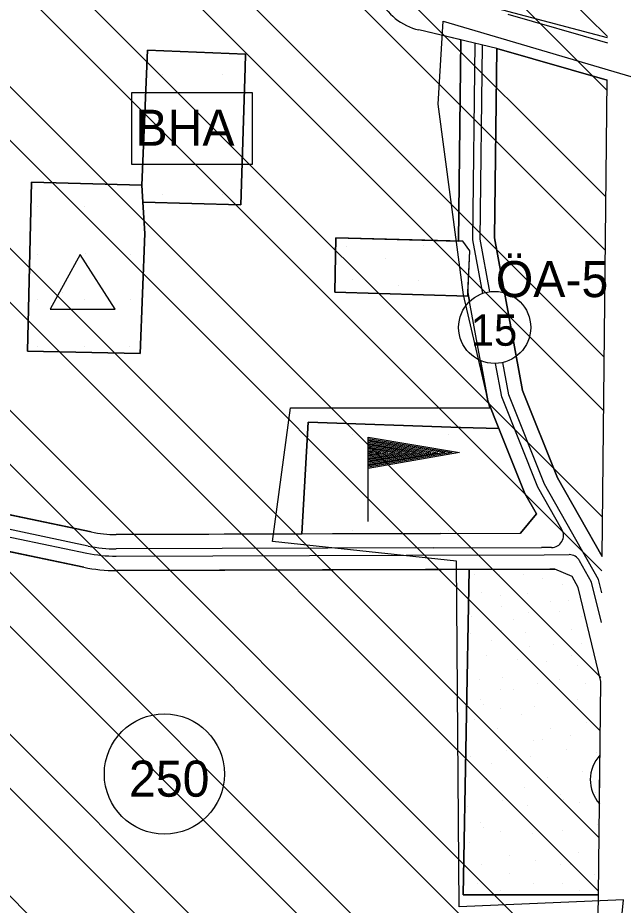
# Model space of a CAD drawing. Extents: x 409341 to 428634, y 4447481 to 4463281.
# Drawn here: x 421057.8 to 421309.7, y 4458160.3 to 4458529.4 of the extents above; entities that cross this region are included whole.
import ezdxf

# ---------------------------------------------------------------- set-up
doc = ezdxf.new("R2010")
doc.units = 0
for name, color, linetype in [('ADA', 7, 'Continuous'), ('ADAKENARI', 7, 'Continuous'), ('Default', 7, 'Continuous'), ('KALDIRIM', 7, 'Continuous'), ('KD_DAIRE', 7, 'Continuous'), ('KD_YGEN', 7, 'Continuous'), ('LJ_SEMBOL', 7, 'Continuous'), ('OA5', 7, 'Continuous'), ('OSB', 7, 'Continuous'), ('PL_AYA_PARK_DINLENME', 7, 'Continuous'), ('PL_EĞİTİM', 7, 'Continuous'), ('PL_K_BHA', 7, 'Continuous'), ('PL_KON_MEV_250', 7, 'Continuous'), ('PL_KON_ONE_250', 7, 'Continuous'), ('PL_KON_ONE_350', 7, 'Continuous'), ('PL_SAY_SPOR', 7, 'Continuous'), ('SM_DAIRE', 7, 'Continuous'), ('SM_TAKS', 7, 'Continuous'), ('SN_TR_SIVILASMA', 7, 'Continuous'), ('TR_EĞİTİM', 7, 'Continuous'), ('TR_KENTSELSPOR', 7, 'Continuous'), ('TR_ORTAGELISME', 7, 'Continuous'), ('TR_ORTAYOGUNKONUT', 7, 'Continuous'), ('TR_PARKALANI', 7, 'Continuous'), ('TR_YONETIMMERK', 7, 'Continuous')]:
    doc.layers.add(name, color=color, linetype=linetype)

# ---------------------------------------------------------------- blocks, each defined once
blk = doc.blocks.new('POINT_DISPLAY')
at = {"layer": 'Default'}
blk.add_line((0, 0), (0, 0), dxfattribs=at)

msp = doc.modelspace()

# ---------------------------------------------------------------- linework, layer by layer
at = {"layer": 'ADA'}
for p, q in [((421245.58, 4458299.98), (421243.14, 4458164.61)), ((421243.14, 4458164.61), (421299.42, 4458164.61))]:
    msp.add_line(p, q, dxfattribs=at)
for points in [[(421109.81, 4458452.73), (421150.57, 4458451.6), (421152.47, 4458508.66), (421152.6, 4458514.27), (421111.77, 4458515.9), (421109.38, 4458459.74)], [(421109.38, 4458459.74), (421063.47, 4458461.09), (421061.84, 4458390.69), (421108.68, 4458389.76), (421110.63, 4458439.7), (421109.81, 4458452.73)]]:
    msp.add_lwpolyline(points, close=True, dxfattribs=at)
msp.add_lwpolyline([(421176.05, 4458314.75), (421178.62, 4458361.17), (421241.98, 4458359.06), (421258.01, 4458358.52)], dxfattribs=at)
at = {"layer": 'ADAKENARI'}
for p, q in [((421261.66, 4458530.99), (421303.12, 4458518.98)), ((421257.09, 4458516.7), (421224.68, 4458524.38)), ((421257.09, 4458516.7), (421302.96, 4458503.42)), ((421088.37, 4458315.57), (421031.06, 4458327.58)), ((420984.64, 4458321.99), (421085.29, 4458300.89)), ((421233.73, 4458314.94), (421098.79, 4458314.5)), ((421233.73, 4458314.94), (421266.9, 4458315.05)), ((421098.84, 4458299.5), (421279.13, 4458300.09)), ((421098.84, 4458299.5), (421227.39, 4458299.92)), ((421279.13, 4458300.09), (421281.2, 4458300.1))]:
    msp.add_line(p, q, dxfattribs=at)
for points in [[(421242.13, 4458520.23), (421241.19, 4458436.6), (421241.2, 4458436.53)], [(421267.85, 4458374.33), (421256.2, 4458437.88), (421257.09, 4458516.7)], [(421245.11, 4458415.17), (421245.8, 4458411.43)], [(421250.3, 4458386.85), (421253.37, 4458370.15), (421258.01, 4458358.52), (421268.78, 4458331.58), (421273.57, 4458323.13), (421266.9, 4458315.05)], [(421300.89, 4458305.33), (421282.33, 4458338.09), (421267.85, 4458374.33)], [(421300.35, 4458253.34), (421290.92, 4458292.51), (421288.4, 4458296.96), (421281.2, 4458300.1)]]:
    msp.add_lwpolyline(points, dxfattribs=at)
msp.add_lwpolyline([(421190.16, 4458437.9), (421189.73, 4458415.29), (421245.05, 4458413.63), (421245.85, 4458432.5), (421242.99, 4458436.48)], close=True, dxfattribs=at)
for centre, radius, start, end in [((421230.47, 4458548.7), 25, 206.131, 256.6075), ((421098.63, 4458364.5), 50, 258.1579, 270.186), ((421098.63, 4458364.5), 65, 258.1579, 270.186)]:
    msp.add_arc(centre, radius, start, end, dxfattribs=at)
at = {"layer": 'Default'}
msp.add_lwpolyline([(421297.69, 4458041.38), (421309.86, 4458162.54), (421241.45, 4458159.64), (421240.3, 4458303.41), (421163.77, 4458311.52), (421171.31, 4458367.18), (421254.21, 4458367.18), (421243.19, 4458414.13), (421232.76, 4458493.55), (421234.79, 4458528.04), (421444.06, 4458466.31), (421567.25, 4458468.77)], dxfattribs=at)
at = {"layer": 'KALDIRIM'}
for p, q in [((420967.32, 4458331.75), (421086.52, 4458306.76)), ((421087.13, 4458309.69), (421029.83, 4458321.71)), ((421230.92, 4458308.93), (421098.81, 4458308.5)), ((421230.92, 4458308.93), (421275.65, 4458309.08)), ((421279.85, 4458309.09), (421275.65, 4458309.08)), ((421098.82, 4458305.5), (421219.35, 4458305.89)), ((421219.35, 4458305.89), (421276.81, 4458306.08)), ((421276.81, 4458306.08), (421287.17, 4458306.11)), ((421300.61, 4458277.91), (421296.56, 4458294.73)), ((421300.73, 4458290.19), (421299.37, 4458295.84))]:
    msp.add_line(p, q, dxfattribs=at)
for points in [[(421251.28, 4458414.8), (421247.19, 4458437.11), (421248.11, 4458518.83)], [(421254.2, 4458415.5), (421250.2, 4458437.37), (421251.11, 4458517.98)], [(421259.16, 4458371.82), (421256.63, 4458385.64)], [(421262.06, 4458372.66), (421259.61, 4458386.03)], [(421284.19, 4458316.56), (421274.2, 4458334.19), (421259.16, 4458371.82)], [(421299.37, 4458295.84), (421276.91, 4458335.49), (421262.06, 4458372.66)], [(421296.56, 4458294.73), (421291.54, 4458303.58)]]:
    msp.add_lwpolyline(points, dxfattribs=at)
for centre, radius, start, end in [((421279.84, 4458314.09), 5, 270.186, 29.5377), ((421098.63, 4458364.5), 56, 258.1579, 270.186), ((421098.63, 4458364.5), 59, 258.1579, 270.186), ((421287.19, 4458301.11), 5, 29.5377, 90.186)]:
    msp.add_arc(centre, radius, start, end, dxfattribs=at)
at = {"layer": 'KD_DAIRE'}
msp.add_line((421299.82, 4458202.47), (421300.03, 4458222.74), dxfattribs=at)
msp.add_circle((421256.22, 4458400.64), 15, dxfattribs=at)
msp.add_arc((421310.98, 4458212.49), 15, 136.8791, 221.9252, dxfattribs=at)
at = {"layer": 'LJ_SEMBOL'}
for p, q in [((421083.85, 4458430.99), (421071.3, 4458408.18)), ((421098.32, 4458408.18), (421083.85, 4458430.99)), ((421071.3, 4458408.18), (421098.32, 4458408.18)), ((421203.57, 4458319.93), (421203.57, 4458354.93))]:
    msp.add_line(p, q, dxfattribs=at)
for points in [[(421105.29, 4458498.34), (421155.29, 4458498.34), (421155.29, 4458468.34), (421105.29, 4458468.34), (421105.29, 4458498.34), (421155.29, 4458498.34)], [(421203.57, 4458354.93), (421241.52, 4458348.55), (421203.57, 4458341.98)], [(421203.57, 4458354.42), (421238.55, 4458348.54), (421203.57, 4458342.49)], [(421203.57, 4458353.92), (421235.58, 4458348.54), (421203.57, 4458342.99)], [(421203.57, 4458353.41), (421232.61, 4458348.53), (421203.57, 4458343.5)], [(421203.57, 4458352.9), (421229.63, 4458348.52), (421203.57, 4458344.01)], [(421203.57, 4458352.4), (421226.66, 4458348.52), (421203.57, 4458344.52)], [(421203.57, 4458351.89), (421223.69, 4458348.51), (421203.57, 4458345.02)], [(421203.57, 4458351.38), (421220.72, 4458348.5), (421203.57, 4458345.53)], [(421203.57, 4458350.88), (421217.74, 4458348.49), (421203.57, 4458346.04)], [(421203.57, 4458350.37), (421214.77, 4458348.49), (421203.57, 4458346.55)], [(421203.57, 4458349.86), (421211.8, 4458348.48), (421203.57, 4458347.05)], [(421203.57, 4458349.35), (421208.83, 4458348.47), (421203.57, 4458347.56)], [(421203.57, 4458348.85), (421205.86, 4458348.46), (421203.57, 4458348.07)]]:
    msp.add_lwpolyline(points, dxfattribs=at)
at = {"layer": 'OSB'}
msp.add_lwpolyline([(421303.14, 4458521.03), (421213.37, 4458544.99), (420881.63, 4458557.8), (420391.63, 4458402.74)], dxfattribs=at)
at = {"layer": 'PL_AYA_PARK_DINLENME'}
msp.add_line((421299.42, 4458164.61), (421300.35, 4458253.34), dxfattribs=at)
for points in [[(421241.2, 4458436.53), (421190.16, 4458437.9), (421189.73, 4458415.29), (421245.05, 4458413.63), (421245.11, 4458415.17), (421245.85, 4458432.5), (421242.99, 4458436.48), (421241.2, 4458436.53)], [(421300.35, 4458253.34), (421290.92, 4458292.51), (421288.4, 4458296.96), (421281.2, 4458300.1), (421279.13, 4458300.09), (421245.58, 4458299.98), (421243.14, 4458164.61), (421299.42, 4458164.61)]]:
    msp.add_lwpolyline(points, dxfattribs=at)
at = {"layer": 'PL_EĞİTİM'}
msp.add_lwpolyline([(421109.81, 4458452.73), (421109.38, 4458459.74), (421063.47, 4458461.09), (421061.84, 4458390.69), (421108.68, 4458389.76), (421110.63, 4458439.7), (421109.81, 4458452.73)], dxfattribs=at)
at = {"layer": 'PL_K_BHA'}
msp.add_lwpolyline([(421109.38, 4458459.74), (421109.81, 4458452.73), (421150.57, 4458451.6), (421152.47, 4458508.66), (421152.6, 4458514.27), (421111.77, 4458515.9), (421109.38, 4458459.74)], dxfattribs=at)
at = {"layer": 'PL_KON_MEV_250'}
msp.add_line((421299.33, 4458155.94), (421299.42, 4458164.61), dxfattribs=at)
for points in [[(421085.29, 4458300.89), (420988.83, 4458321.11), (420988.83, 4458315.56), (420979.14, 4458315.7), (420960.46, 4458090.34)], [(421245.58, 4458299.98), (421227.39, 4458299.92), (421098.84, 4458299.5)], [(421299.42, 4458164.61), (421243.14, 4458164.61), (421245.58, 4458299.98)]]:
    msp.add_lwpolyline(points, dxfattribs=at)
msp.add_arc((421098.63, 4458364.5), 65, 258.1579, 270.186, dxfattribs=at)
at = {"layer": 'PL_KON_ONE_250'}
for points in [[(421245.11, 4458415.17), (421245.05, 4458413.63), (421189.73, 4458415.29), (421190.16, 4458437.9), (421241.2, 4458436.53), (421241.19, 4458436.6), (421242.13, 4458520.23), (421224.68, 4458524.38)], [(421109.38, 4458459.74), (421111.77, 4458515.9), (421152.6, 4458514.27), (421152.47, 4458508.66), (421150.57, 4458451.6), (421109.81, 4458452.73), (421110.63, 4458439.7), (421108.68, 4458389.76), (421061.84, 4458390.69), (421063.47, 4458461.09), (421109.38, 4458459.74)], [(421098.79, 4458314.5), (421176.05, 4458314.75), (421178.62, 4458361.17), (421241.98, 4458359.06), (421258.01, 4458358.52), (421253.37, 4458370.15), (421245.11, 4458415.17)], [(420943.04, 4458393.72), (420970.15, 4458344.23), (420967.66, 4458340.88), (421031.06, 4458327.58), (421088.37, 4458315.57)]]:
    msp.add_lwpolyline(points, dxfattribs=at)
for centre, radius, start, end in [((421230.47, 4458548.7), 25, 206.131, 256.6075), ((421098.63, 4458364.5), 50, 258.1579, 270.186)]:
    msp.add_arc(centre, radius, start, end, dxfattribs=at)
at = {"layer": 'PL_KON_ONE_350'}
msp.add_line((421300.89, 4458305.33), (421302.96, 4458503.42), dxfattribs=at)
msp.add_lwpolyline([(421302.96, 4458503.42), (421257.09, 4458516.7), (421256.2, 4458437.88), (421267.85, 4458374.33), (421282.33, 4458338.09), (421300.89, 4458305.33)], dxfattribs=at)
at = {"layer": 'PL_SAY_SPOR'}
msp.add_lwpolyline([(421176.05, 4458314.75), (421233.73, 4458314.94), (421266.9, 4458315.05), (421273.57, 4458323.13), (421268.78, 4458331.58), (421258.01, 4458358.52), (421241.98, 4458359.06), (421178.62, 4458361.17), (421176.05, 4458314.75)], dxfattribs=at)
at = {"layer": 'SM_DAIRE'}
msp.add_circle((421118.84, 4458214.87), 25, dxfattribs=at)
at = {"layer": 'SN_TR_SIVILASMA'}
for p, q in [((421299.44, 4458166.1), (420879.12, 4458586.42)), ((421299.67, 4458188.32), (420901.57, 4458586.42)), ((421300.13, 4458232.76), (420946.47, 4458586.42)), ((421300.13, 4458232.76), (420946.47, 4458586.42)), ((421300.37, 4458254.98), (420968.92, 4458586.42)), ((421300.37, 4458254.98), (420968.92, 4458586.42)), ((421300.83, 4458299.42), (421013.82, 4458586.42)), ((421301.06, 4458321.64), (421036.28, 4458586.42)), ((421301.53, 4458366.07), (421081.18, 4458586.42)), ((421301.76, 4458388.29), (421103.63, 4458586.42)), ((421302.22, 4458432.73), (421148.53, 4458586.42)), ((421302.45, 4458454.95), (421170.98, 4458586.42)), ((421302.92, 4458499.39), (421215.88, 4458586.42)), ((421303.15, 4458521.61), (421238.33, 4458586.42)), ((421298.05, 4458032.79), (420847.49, 4458483.35)), ((421297.58, 4457988.35), (420847.49, 4458438.45)), ((421297.35, 4457966.14), (420847.49, 4458416)), ((421298.97, 4458121.67), (421019.26, 4458401.39)), ((421298.28, 4458055.01), (420959.98, 4458393.31)), ((421298.74, 4458099.45), (421005.98, 4458392.22)), ((421296.89, 4457921.7), (420847.49, 4458371.1))]:
    msp.add_line(p, q, dxfattribs=at)
at = {"layer": 'TR_ORTAGELISME'}
msp.add_line((421300.89, 4458305.33), (421302.96, 4458503.42), dxfattribs=at)
for points in [[(421098.79, 4458314.5), (421176.05, 4458314.75), (421178.62, 4458361.17), (421241.98, 4458359.06), (421258.01, 4458358.52), (421253.37, 4458370.15), (421245.11, 4458415.17), (421245.05, 4458413.63), (421189.73, 4458415.29), (421190.16, 4458437.9), (421241.2, 4458436.53), (421241.19, 4458436.6), (421242.13, 4458520.23), (421224.68, 4458524.38)], [(421063.47, 4458461.09), (421109.38, 4458459.74), (421111.77, 4458515.9), (421152.6, 4458514.27), (421152.47, 4458508.66), (421150.57, 4458451.6), (421109.81, 4458452.73), (421110.63, 4458439.7), (421108.68, 4458389.76), (421061.84, 4458390.69), (421063.47, 4458461.09)], [(421302.96, 4458503.42), (421257.09, 4458516.7), (421256.2, 4458437.88), (421267.85, 4458374.33), (421282.33, 4458338.09), (421300.89, 4458305.33)], [(420967.66, 4458340.88), (421031.06, 4458327.58), (421088.37, 4458315.57)]]:
    msp.add_lwpolyline(points, dxfattribs=at)
for centre, radius, start, end in [((421230.47, 4458548.7), 25, 206.131, 256.6075), ((421098.63, 4458364.5), 50, 258.1579, 270.186)]:
    msp.add_arc(centre, radius, start, end, dxfattribs=at)
at = {"layer": 'TR_ORTAYOGUNKONUT'}
for p, q in [((421227.39, 4458299.92), (421098.84, 4458299.5)), ((421299.33, 4458155.94), (421299.42, 4458164.61))]:
    msp.add_line(p, q, dxfattribs=at)
for points in [[(421085.29, 4458300.89), (420988.83, 4458321.11), (420988.83, 4458315.56), (420979.14, 4458315.7), (420960.46, 4458090.34)], [(421299.42, 4458164.61), (421243.14, 4458164.61), (421245.58, 4458299.98), (421227.39, 4458299.92)]]:
    msp.add_lwpolyline(points, dxfattribs=at)
msp.add_circle((421118.84, 4458214.87), 25, dxfattribs=at)
msp.add_arc((421098.63, 4458364.5), 65, 258.1579, 270.186, dxfattribs=at)

# ---------------------------------------------------------------- block references
at = {"layer": 'TR_EĞİTİM', "xscale": 0.1, "yscale": 0.10000000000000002}
for p in [(421065.99, 4458450.89), (421085.75, 4458451.11), (421104.55, 4458450.89), (421065.99, 4458430.89), (421086.19, 4458431.2), (421104.55, 4458430.89), (421076.5, 4458415.36), (421065.99, 4458412.18), (421085.75, 4458412.4), (421104.55, 4458412.18), (421085.6, 4458392.86), (421065.85, 4458392.64), (421104.4, 4458392.64)]:
    msp.add_blockref('POINT_DISPLAY', p, dxfattribs=at)
at = {"layer": 'TR_KENTSELSPOR', "xscale": 0.1, "yscale": 0.10000000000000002}
for p in [(421197.06, 4458356.19), (421197.06, 4458356.19), (421197.06, 4458356.19), (421197.06, 4458356.19), (421237.06, 4458356.19), (421237.06, 4458356.19), (421237.06, 4458356.19), (421237.06, 4458356.19), (421221.79, 4458346.98), (421221.79, 4458346.98), (421221.79, 4458346.98), (421221.79, 4458346.98), (421197.06, 4458316.19), (421197.06, 4458316.19), (421197.06, 4458316.19), (421197.06, 4458316.19), (421237.06, 4458316.19), (421237.06, 4458316.19), (421237.06, 4458316.19), (421237.06, 4458316.19)]:
    msp.add_blockref('POINT_DISPLAY', p, dxfattribs=at)
at = {"layer": 'TR_PARKALANI', "xscale": 0.1, "yscale": 0.10000000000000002}
for p in [(421194.71, 4458434.48), (421226.67, 4458434.73), (421210.69, 4458429.15), (421197.13, 4458420.59), (421224.53, 4458420.08), (421216.16, 4458418.05), (421247.63, 4458298.03), (421258.23, 4458298.03), (421268.27, 4458298.03), (421275.99, 4458296.26), (421284.27, 4458293.72), (421250.61, 4458290.3), (421269.7, 4458290.08), (421258.67, 4458288.98), (421279.64, 4458286.77), (421287.03, 4458287.1), (421258.89, 4458284.46), (421270.48, 4458282.25), (421283.17, 4458282.36), (421246.53, 4458280.59), (421253.26, 4458279.6), (421264.08, 4458279.16), (421292.33, 4458280.59), (421277.21, 4458277.94), (421288.13, 4458274.97), (421246.34, 4458273.17), (421246.34, 4458273.17), (421258.89, 4458274.63), (421269.04, 4458273.86), (421254.8, 4458270.38), (421270.79, 4458267.93), (421280.74, 4458268.9), (421292.33, 4458269.34), (421253, 4458264.19), (421253, 4458264.19), (421288.13, 4458264.04), (421265.72, 4458262.63), (421277.63, 4458261.53), (421290.88, 4458259.98), (421244.89, 4458252.61), (421244.89, 4458252.61), (421249.95, 4458254.33), (421259.66, 4458255.21), (421259.66, 4458255.21), (421283.28, 4458254.33), (421258.66, 4458249.83), (421263.95, 4458249.83), (421274.1, 4458252.48), (421293.97, 4458252.48), (421250.46, 4458245.76), (421287.56, 4458245.47), (421287.56, 4458245.47), (421290.51, 4458245.87), (421251.55, 4458243.63), (421251.55, 4458243.63), (421258.48, 4458242.11), (421272.79, 4458242.87), (421272.79, 4458242.87), (421267.26, 4458239.68), (421247.75, 4458237.34), (421294.22, 4458236.49), (421294.22, 4458236.49), (421254.45, 4458233.56), (421254.45, 4458233.56), (421257.41, 4458233.95), (421279.45, 4458233.89), (421279.45, 4458233.89), (421287.91, 4458231.09), (421272.27, 4458228.77), (421276.13, 4458229.02), (421261.11, 4458224.58), (421261.11, 4458224.58), (421286.11, 4458224.91), (421286.11, 4458224.91), (421298.5, 4458223.87), (421246.34, 4458221.97), (421246.34, 4458221.97), (421271.33, 4458222.31), (421271.33, 4458222.31), (421254.8, 4458219.18), (421292.77, 4458215.93), (421292.77, 4458215.93), (421253, 4458212.99), (421253, 4458212.99), (421277.99, 4458213.33), (421277.99, 4458213.33), (421268.79, 4458209.08), (421283.57, 4458206.47), (421298.06, 4458207.1), (421244.89, 4458201.41), (421244.89, 4458201.41), (421259.66, 4458204.01), (421259.66, 4458204.01), (421269.88, 4458201.74), (421269.88, 4458201.74), (421284.66, 4458204.35), (421284.66, 4458204.35), (421291.59, 4458202.82), (421250.46, 4458194.56), (421299.03, 4458193.83), (421299.03, 4458193.83), (421251.55, 4458192.43), (421258.48, 4458190.91), (421272.12, 4458190.25), (421284.26, 4458191.23), (421284.26, 4458191.23), (421245.63, 4458186.27), (421262.19, 4458180.98), (421273.35, 4458178.85), (421290.92, 4458182.25), (421290.92, 4458182.25), (421299.38, 4458179.45), (421250.93, 4458177.22), (421283.74, 4458177.13), (421287.61, 4458177.38), (421262.19, 4458173.47), (421297.58, 4458173.27), (421297.58, 4458173.27), (421249.07, 4458169.14), (421272.46, 4458169.14), (421284.38, 4458169.14), (421258.56, 4458166.49), (421291.66, 4458166.49)]:
    msp.add_blockref('POINT_DISPLAY', p, dxfattribs=at)
at = {"layer": 'TR_YONETIMMERK', "xscale": 0.1, "yscale": 0.10000000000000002}
for p in [(421117.91, 4458505.89), (421142.91, 4458505.89), (421117.91, 4458480.89), (421142.91, 4458480.89), (421117.91, 4458455.88), (421142.91, 4458455.88)]:
    msp.add_blockref('POINT_DISPLAY', p, dxfattribs=at)

# ---------------------------------------------------------------- texts
at = {"layer": 'Default'}
for s, p in [('18.10.2018 TARİHLİ KARARI İLE YÜRÜTMESİ DURDURULMUŞTUR. (BBMK: 28.12.2018/2840)', (421256.46, 4457501.97)), ("BURSA 1. İDARE MAHKEMESİ'NİN 2017/849 E. SAYI VE ", (421293.63, 4457678.34))]:
    msp.add_text(s, height=15, rotation=70.3879, dxfattribs=at).set_placement(p)
at = {"layer": 'KD_YGEN'}
msp.add_text('15', height=13, dxfattribs=at).set_placement((421246.28, 4458393.01))
at = {"layer": 'LJ_SEMBOL'}
msp.add_text('BHA', height=15, dxfattribs=at).set_placement((421106.76, 4458476.19))
at = {"layer": 'OA5'}
msp.add_text('ÖA-5', height=15, dxfattribs=at).set_placement((421256.68, 4458413.23))
at = {"layer": 'SM_TAKS'}
msp.add_text('250', height=15, dxfattribs=at).set_placement((421104.1, 4458205.43))

doc.saveas('drawing.dxf')
